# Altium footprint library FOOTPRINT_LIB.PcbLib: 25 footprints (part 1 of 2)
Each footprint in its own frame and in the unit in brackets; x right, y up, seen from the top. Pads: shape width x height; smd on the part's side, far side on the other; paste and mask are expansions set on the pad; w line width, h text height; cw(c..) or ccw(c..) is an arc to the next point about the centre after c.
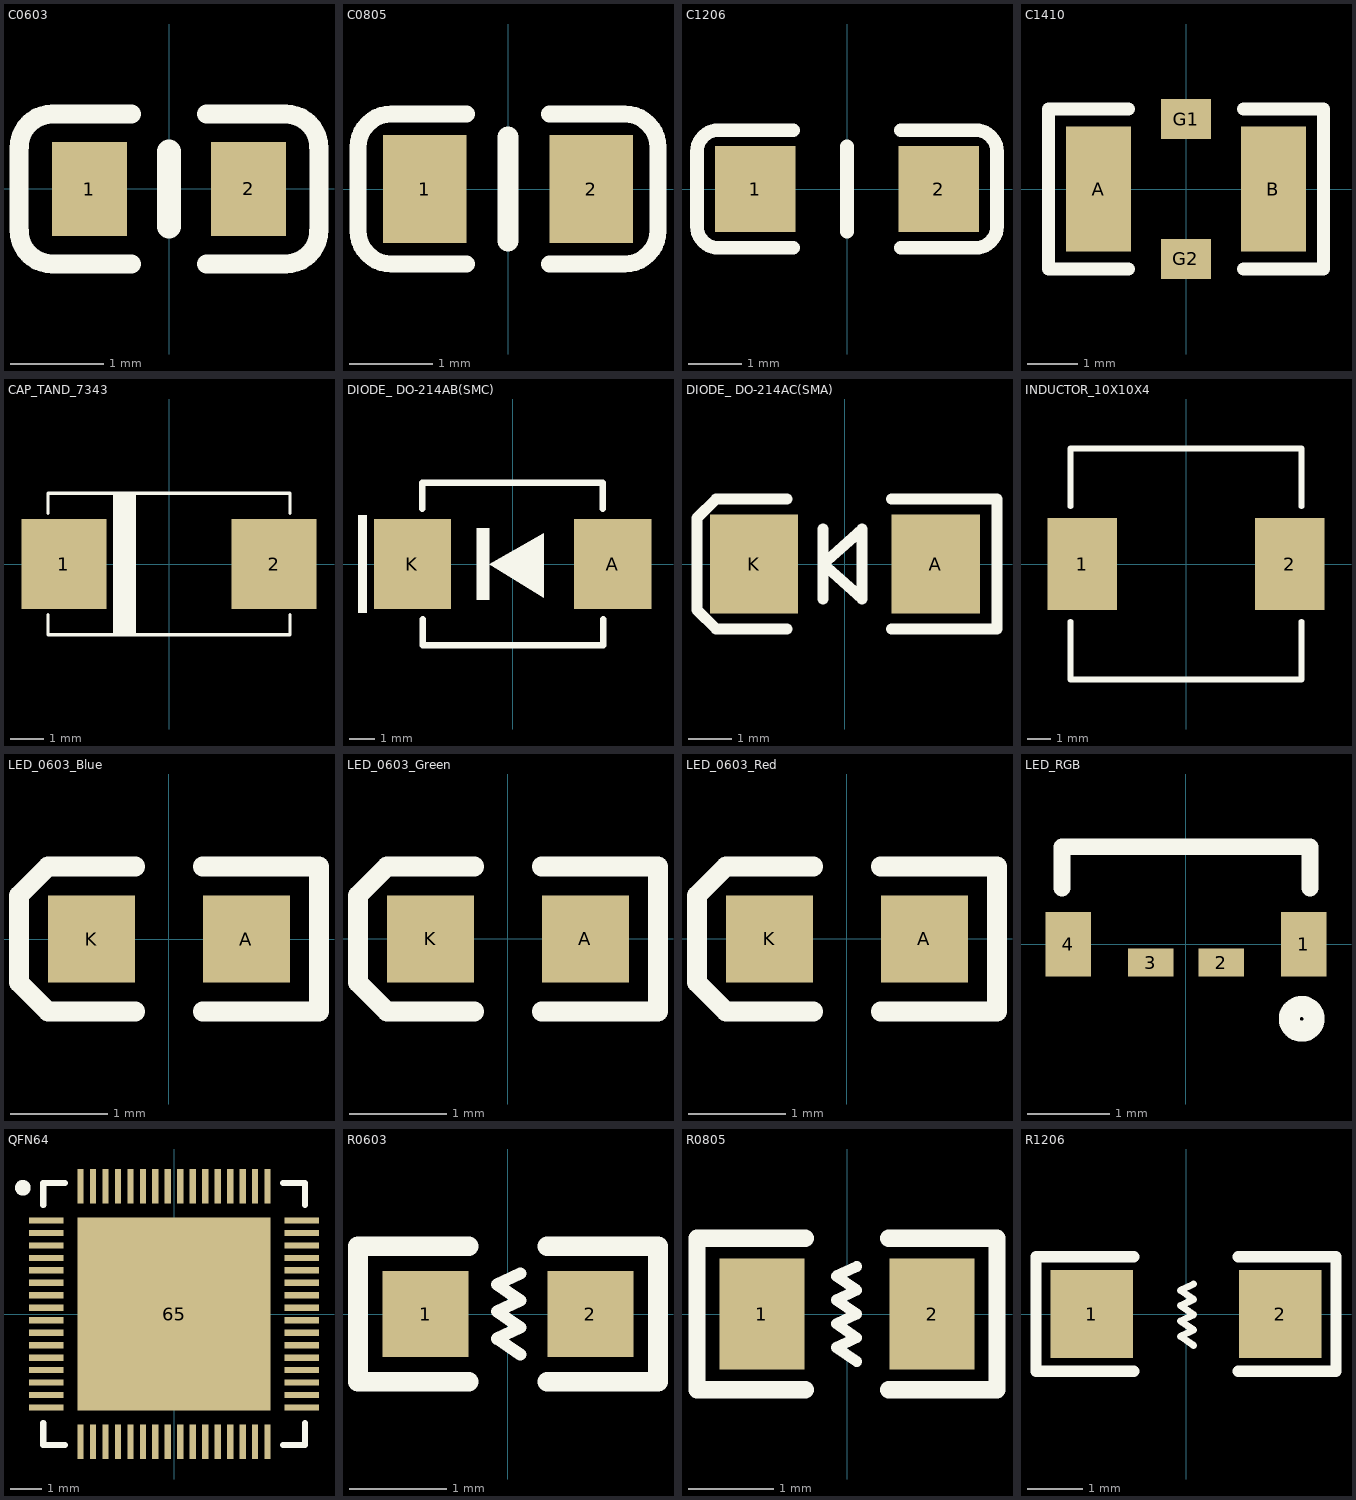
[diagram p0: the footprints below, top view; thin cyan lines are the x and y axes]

## C0603 [mm] "Chip Capacitor, 2-Leads, Body 1.60x0.80mm, IPC Medium Density"
height 0.6
pads (2):
  rect 0.8x1 smd: 1(-0.85,0) 2(0.85,0)
Top Overlay:
  lines w0.203: -1.604,-0.45 -1.604,0.45 ; -1.6,-0.45 ccw(c-1.25,-0.45) -1.25,-0.8 -0.4,-0.8 ; -1.6,0.45 cw(c-1.25,0.45) -1.25,0.8 -0.4,0.8 ; 0.4,-0.8 1.25,-0.8 ccw(c1.25,-0.45) 1.6,-0.45 ; 0.4,0.8 1.25,0.8 cw(c1.25,0.45) 1.6,0.45 ; 1.604,-0.45 1.604,0.45
  lines w0.254: 0,-0.4 0,0.4
3D body "C0603.stp": height 0.8, standoff 0, extent -0.8,-0.4 0.8,0.4

## C0805 [mm] "Chip Capacitor, 2-Leads, Body 2.00x1.25mm, IPC Medium Density"
height 0.8
pads (2):
  rect 1x1.3 smd: 1(-1,0) 2(1,0)
Top Overlay:
  lines w0.203: -0.5,-0.9 -1.4,-0.9 cw(c-1.4,-0.5) -1.8,-0.5 -1.8,0.5 cw(c-1.4,0.5) -1.4,0.9 -0.5,0.9 ; 0.5,-0.9 1.4,-0.9 ccw(c1.4,-0.5) 1.8,-0.5 1.8,0.5 ccw(c1.4,0.5) 1.4,0.9 0.5,0.9
  lines w0.254: 0,-0.625 0,0.625
3D body "C0805.stp": height 0.94, standoff 0, extent -1.005,-0.625 1.005,0.625

## C1206 [mm]
pads (2):
  rect 1.5x1.6 smd: 1(-1.714,0) 2(1.714,0)
Top Overlay:
  lines w0.254: -1,-1.1 -2.4,-1.1 cw(c-2.4,-0.7) -2.8,-0.7 -2.8,0.7 cw(c-2.4,0.7) -2.4,1.1 -1,1.1 ; 0,-0.8 0,0.8 ; 1,-1.1 2.4,-1.1 ccw(c2.4,-0.7) 2.8,-0.7 2.8,0.7 ccw(c2.4,0.7) 2.4,1.1 1,1.1
3D body "C1206.stp": height 1.27, standoff 0, extent -1.6,-0.8 1.6,0.8

## C1410 [mm]
pads (4):
  rect 1.3x2.5 smd: A(-1.75,0) B(1.75,0)
  rect 1x0.8 smd: G1(0,1.4) G2(0,-1.4)
Top Overlay:
  lines w0.254: -1.15,-1.6 -2.75,-1.6 -2.75,1.6 -1.15,1.6 ; 1.15,-1.6 2.75,-1.6 2.75,1.6 1.15,1.6
3D body "C1210_140.step": height 1.4, standoff 0, extent -1.6,-1.25 1.6,1.25

## CAP_TAND_7343 [mil] "7343 Metric, 7.30mm x 4.30mm"
height 122.05
pads (2):
  rect 101x107 smd: 1(-125,0) 2(125,0)
Top Overlay:
  rectangle: -66.93,-84 -39.37,82.68
  lines w3.94: -144,-84 -144,-60.32 ; -144,60 -144,84 ; 144,-84 144,-60.32 ; 144,60 144,84
  lines w4: -144,-84 144,-84 ; -144,84 144,84
3D body "CaseD_7343-31.STEP": height 110.24, standoff 0, extent -143.7,-84.65 143.7,84.65

## DIODE_ DO-214AB(SMC) [mm]
pads (2):
  rect 3x3.5 smd: A(3.888,0) K(-3.888,0)
Top Overlay:
  rectangle: -6,-1.9 -5.65,1.9
  rectangle: -1.4,-1.4 -0.9,1.4
  region: 1.2,1.2 1.2,-1.3 -0.9,0
  lines w0.254: -3.514,2.15 -3.514,3.15 3.486,3.15 3.486,2.15 ; -3.486,-2.15 -3.486,-3.15 3.514,-3.15 3.514,-2.15
3D body "User Library-DO-214AB(SMC).step": height 2.67, standoff 0.03, extent -4.064,-3.149 4.064,3.15

## DIODE_ DO-214AC(SMA) [mil]
pads (2):
  rect 80x90 smd: A(82.19,0) K(-82.19,0)
Top Overlay:
  lines w10: -52.19,-59.06 -116.44,-59.06 -133.86,-41.63 -133.86,41.63 -116.44,59.06 -52.19,59.06 ; -19.68,-31.5 -19.68,31.5 ; 42.19,-59.06 137.8,-59.06 137.8,59.06 42.19,59.06 ; -19.68,0 15.75,-31.5 15.75,31.5 -19.68,0
3D body "SMA (DO-214AC).step": height 102.36, standoff 1.02, extent -108.26,-55.11 108.27,55.12

## INDUCTOR_10X10X4 [mm]
pads (2):
  rect 3x4 smd: 1(-4.5,0) 2(4.5,0)
Top Overlay:
  lines w0.254: -5,-2.5 -5,-5 5,-5 5,-2.5 ; -5,2.5 -5,5 5,5 5,2.5
3D body "10x10mm.step": height 3.97, standoff 0.06, extent -5.38,-5 5.38,5

## LED_0603_Blue [mm] "SMD Blue LED with Package 0603"
pads (2):
  rect 0.9x0.9 smd: A(0.8,0) K(-0.8,0)
Top Overlay:
  lines w0.203: -0.35,-0.75 -1.25,-0.75 -1.55,-0.45 -1.55,0.45 -1.25,0.75 -0.35,0.75 ; 0.35,-0.75 1.55,-0.75 1.55,0.75 0.35,0.75
3D body "LED_0603_B.STEP": height 0.6, standoff 0, extent -0.8,-0.4 0.8,0.4

## LED_0603_Green [mm] "SMD Green LED with Package 0603"
pads (2):
  rect 0.9x0.9 smd: A(0.8,0) K(-0.8,0)
Top Overlay:
  lines w0.203: -0.35,-0.75 -1.25,-0.75 -1.55,-0.45 -1.55,0.45 -1.25,0.75 -0.35,0.75 ; 0.35,-0.75 1.55,-0.75 1.55,0.75 0.35,0.75
3D body "LTST-C190GKT.STEP": height 0.9, standoff 0, extent -0.85,-0.45 0.85,0.45

## LED_0603_Red [mm] "SMD Blue LED with Package 0603"
pads (2):
  rect 0.9x0.9 smd: A(0.8,0) K(-0.8,0)
Top Overlay:
  lines w0.203: -0.35,-0.75 -1.25,-0.75 -1.55,-0.45 -1.55,0.45 -1.25,0.75 -0.35,0.75 ; 0.35,-0.75 1.55,-0.75 1.55,0.75 0.35,0.75
3D body "LED_0603_R.STEP": height 0.6, standoff 0, extent -0.8,-0.4 0.8,0.4

## LED_RGB [mm]
pads (4):
  rect 0.55x0.78 smd: 1(1.425,0) 4(-1.425,0)
  rect 0.55x0.34 smd: 2(0.425,-0.22) 3(-0.425,-0.22)
Top Overlay:
  circle w0.254: c1.4,-0.9 r0.15
  lines w0.203: -1.5,0.682 -1.5,1.182 1.5,1.182 1.5,0.682
3D body "LED_RGB.SLDPRT": height 1, standoff 0, extent -1.5,-0.2 1.5,1.182

## QFN64 [mm] "QFN, 64-Leads, Body 8.00x8.00mm, Pitch 0.40mm, Thermal Pad 6.20x6.20mm, IPC Low Density"
height 0.8
pads (65):
  rect 1.1x0.2 smd: 1(-4.1,3) 2(-4.1,2.6) 3(-4.1,2.2) 4(-4.1,1.8) 5(-4.1,1.4) 6(-4.1,1) 7(-4.1,0.6) 8(-4.1,0.2) 9(-4.1,-0.2) 10(-4.1,-0.6) 11(-4.1,-1) 12(-4.1,-1.4) 13(-4.1,-1.8) 14(-4.1,-2.2) 15(-4.1,-2.6) 16(-4.1,-3) 33(4.1,-3) 34(4.1,-2.6) 35(4.1,-2.2) 36(4.1,-1.8) 37(4.1,-1.4) 38(4.1,-1) 39(4.1,-0.6) 40(4.1,-0.2) 41(4.1,0.2) 42(4.1,0.6) 43(4.1,1) 44(4.1,1.4) 45(4.1,1.8) 46(4.1,2.2) 47(4.1,2.6) 48(4.1,3)
  rect 0.2x1.1 smd: 17(-3,-4.1) 18(-2.6,-4.1) 19(-2.2,-4.1) 20(-1.8,-4.1) 21(-1.4,-4.1) 22(-1,-4.1) 23(-0.6,-4.1) 24(-0.2,-4.1) 25(0.2,-4.1) 26(0.6,-4.1) 27(1,-4.1) 28(1.4,-4.1) 29(1.8,-4.1) 30(2.2,-4.1) 31(2.6,-4.1) 32(3,-4.1) 49(3,4.1) 50(2.6,4.1) 51(2.2,4.1) 52(1.8,4.1) 53(1.4,4.1) 54(1,4.1) 55(0.6,4.1) 56(0.2,4.1) 57(-0.2,4.1) 58(-0.6,4.1) 59(-1,4.1) 60(-1.4,4.1) 61(-1.8,4.1) 62(-2.2,4.1) 63(-2.6,4.1) 64(-3,4.1)
  rect 6.2x6.2 smd: 65(0,0)
Top Overlay:
  circle w0.25: c-4.85,4.05 r0.125
  lines w0.2: -4.2,-3.5 -4.2,-4.2 -3.5,-4.2 ; -4.2,3.5 -4.2,4.2 -3.5,4.2 ; 3.5,-4.2 4.2,-4.2 4.2,-3.5 ; 3.5,4.2 4.2,4.2 4.2,3.5
3D body "QFN40P800X800X80_HS-65M.step": height 0.8, standoff 0, extent -4.06,-4.06 4.06,4.06

## R0603 [mil] "Chip Resistor, 2-Leads, Body 1.55x0.85mm, IPC Medium Density"
height 23.62
pads (2):
  rect 35x35 smd: 1(-33.46,0) 2(33.46,0)
Top Overlay:
  lines w5: 5,-16.5 -4.5,-10 5,-5.5 -4.5,1 5,5.5 -4.5,12 5,16.5
  lines w8: -15.96,-27.5 -60.96,-27.5 -60.96,27.5 -15.96,27.5 ; 15.96,-27.5 60.96,-27.5 60.96,27.5 15.96,27.5
3D body "R0603.step": height 15.75, standoff 0, extent -31.49,-15.75 31.51,15.75

## R0805 [mm] "Chip Capacitor, 2-Leads, Body 2.00x1.25mm, IPC Medium Density"
height 0.8
pads (2):
  rect 1x1.3 smd: 1(-1,0) 2(1,0)
Top Overlay:
  lines w0.127: 0.114,-0.559 -0.127,-0.394 0.114,-0.279 -0.127,-0.114 0.114,0 -0.127,0.165 0.114,0.279 -0.127,0.445 0.114,0.559
  lines w0.203: -0.492,-0.889 -1.762,-0.889 -1.762,0.889 -0.492,0.889 ; 0.492,-0.889 1.762,-0.889 1.762,0.889 0.492,0.889
3D body "R0805.step": height 0.5, standoff 0, extent -1,-0.625 1,0.625

## R1206 [mm]
pads (2):
  rect 1.5x1.6 smd: 1(-1.714,0) 2(1.714,0)
Top Overlay:
  lines w0.127: 0.14,-0.572 -0.102,-0.406 0.14,-0.292 -0.102,-0.127 0.14,-0.013 -0.102,0.152 0.14,0.267 -0.102,0.432 0.14,0.546
  lines w0.203: -0.953,-1.041 -2.73,-1.041 -2.73,1.041 -0.953,1.041 ; 0.953,-1.041 2.73,-1.041 2.73,1.041 0.953,1.041
3D body "R1206.step": height 0.56, standoff 0, extent -1.6,-0.8 1.6,0.8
